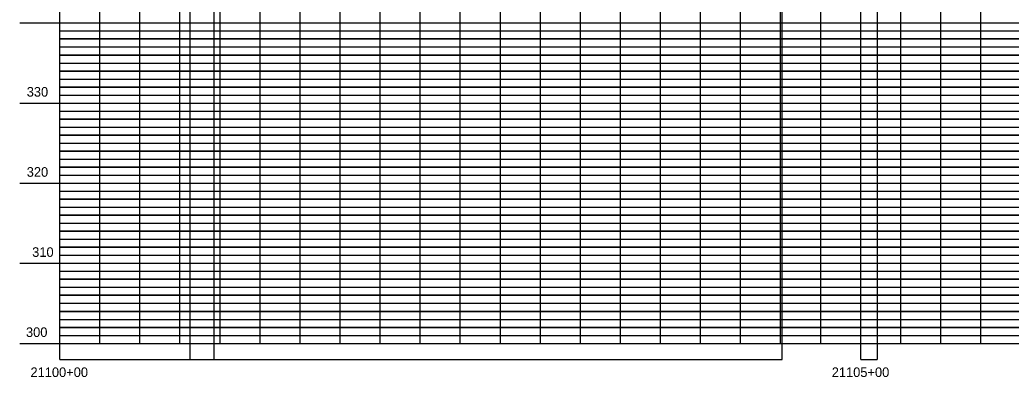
# Model space of a CAD drawing. Extents: x 1195880 to 1289360, y 2059330 to 2086925.
# Drawn here: x 1196981 to 1197600, y 2059330 to 2059553 of the extents above; entities that cross this region are included whole.
import ezdxf

# ---------------------------------------------------------------- set-up
doc = ezdxf.new("R2010")
doc.units = 0
for name, color, linetype in [('51', 7, 'Continuous'), ('Default', 7, 'Continuous'), ('Grid', 7, 'Continuous'), ('Grid Lables', 7, 'Continuous')]:
    doc.layers.add(name, color=color, linetype=linetype)

msp = doc.modelspace()

# ---------------------------------------------------------------- linework, layer by layer
at = {"layer": 'Default'}
for p, q in [((1197102.55, 2059676.6), (1197102.55, 2059340.74)), ((1197087.81, 2059340.74), (1197087.81, 2059676.01)), ((1197457.27, 2059340.74), (1197457.27, 2059664.54)), ((1197516.64, 2059662.37), (1197516.64, 2059340.74)), ((1197006.37, 2059340.74), (1197087.81, 2059340.74)), ((1197006.37, 2059340.74), (1197457.27, 2059340.74)), ((1197006.37, 2059340.74), (1197102.55, 2059340.74)), ((1197506.37, 2059340.74), (1197516.64, 2059340.74))]:
    msp.add_line(p, q, dxfattribs=at)
at = {"layer": 'Grid'}
for p, q in [((1197006.37, 2059350.74), (1197006.37, 2059950.74)), ((1197031.37, 2059350.74), (1197031.37, 2059950.74)), ((1197056.37, 2059350.74), (1197056.37, 2059950.74)), ((1197081.37, 2059350.74), (1197081.37, 2059950.74)), ((1197106.37, 2059350.74), (1197106.37, 2059950.74)), ((1197131.37, 2059350.74), (1197131.37, 2059950.74)), ((1197156.37, 2059350.74), (1197156.37, 2059950.74)), ((1197181.37, 2059350.74), (1197181.37, 2059950.74)), ((1197206.37, 2059350.74), (1197206.37, 2059950.74)), ((1197231.37, 2059350.74), (1197231.37, 2059950.74)), ((1197256.37, 2059350.74), (1197256.37, 2059950.74)), ((1197281.37, 2059350.74), (1197281.37, 2059950.74)), ((1197306.37, 2059350.74), (1197306.37, 2059950.74)), ((1197331.37, 2059350.74), (1197331.37, 2059950.74)), ((1197356.37, 2059350.74), (1197356.37, 2059950.74)), ((1197381.37, 2059350.74), (1197381.37, 2059950.74)), ((1197406.37, 2059350.74), (1197406.37, 2059950.74)), ((1197431.37, 2059350.74), (1197431.37, 2059950.74)), ((1197456.37, 2059350.74), (1197456.37, 2059950.74)), ((1197481.37, 2059350.74), (1197481.37, 2059950.74)), ((1197506.37, 2059350.74), (1197506.37, 2059950.74)), ((1197531.37, 2059350.74), (1197531.37, 2059950.74)), ((1197556.37, 2059350.74), (1197556.37, 2059950.74)), ((1197581.37, 2059350.74), (1197581.37, 2059950.74)), ((1196981.37, 2059550.74), (1197006.37, 2059550.74)), ((1197006.37, 2059550.74), (1198006.37, 2059550.74)), ((1197006.37, 2059545.74), (1197009.37, 2059545.74)), ((1197006.37, 2059545.74), (1198006.37, 2059545.74)), ((1197006.37, 2059540.74), (1197009.37, 2059540.74)), ((1197006.37, 2059540.74), (1198006.37, 2059540.74)), ((1198006.37, 2059540.74), (1197006.37, 2059540.74)), ((1197006.37, 2059535.74), (1197009.37, 2059535.74)), ((1197006.37, 2059535.74), (1198006.37, 2059535.74)), ((1197006.37, 2059530.74), (1197009.37, 2059530.74)), ((1197006.37, 2059530.74), (1198006.37, 2059530.74)), ((1198006.37, 2059530.74), (1197006.37, 2059530.74)), ((1197006.37, 2059525.74), (1197009.37, 2059525.74)), ((1197006.37, 2059525.74), (1198006.37, 2059525.74)), ((1197006.37, 2059520.74), (1197009.37, 2059520.74)), ((1197006.37, 2059520.74), (1198006.37, 2059520.74)), ((1198006.37, 2059520.74), (1197006.37, 2059520.74)), ((1197006.37, 2059515.74), (1197009.37, 2059515.74)), ((1197006.37, 2059515.74), (1198006.37, 2059515.74)), ((1197006.37, 2059510.74), (1197009.37, 2059510.74)), ((1197006.37, 2059510.74), (1198006.37, 2059510.74)), ((1198006.37, 2059510.74), (1197006.37, 2059510.74)), ((1197006.37, 2059505.74), (1197009.37, 2059505.74)), ((1197006.37, 2059505.74), (1198006.37, 2059505.74)), ((1196981.37, 2059500.74), (1197006.37, 2059500.74)), ((1197006.37, 2059500.74), (1198006.37, 2059500.74)), ((1197006.37, 2059495.74), (1197009.37, 2059495.74)), ((1197006.37, 2059495.74), (1198006.37, 2059495.74)), ((1197006.37, 2059490.74), (1197009.37, 2059490.74)), ((1197006.37, 2059490.74), (1198006.37, 2059490.74)), ((1198006.37, 2059490.74), (1197006.37, 2059490.74)), ((1197006.37, 2059485.74), (1197009.37, 2059485.74)), ((1197006.37, 2059485.74), (1198006.37, 2059485.74)), ((1197006.37, 2059480.74), (1197009.37, 2059480.74)), ((1197006.37, 2059480.74), (1198006.37, 2059480.74)), ((1198006.37, 2059480.74), (1197006.37, 2059480.74)), ((1197006.37, 2059475.74), (1197009.37, 2059475.74)), ((1197006.37, 2059475.74), (1198006.37, 2059475.74)), ((1197006.37, 2059470.74), (1197009.37, 2059470.74)), ((1197006.37, 2059470.74), (1198006.37, 2059470.74)), ((1198006.37, 2059470.74), (1197006.37, 2059470.74)), ((1197006.37, 2059465.74), (1197009.37, 2059465.74)), ((1197006.37, 2059465.74), (1198006.37, 2059465.74)), ((1197006.37, 2059460.74), (1197009.37, 2059460.74)), ((1197006.37, 2059460.74), (1198006.37, 2059460.74)), ((1198006.37, 2059460.74), (1197006.37, 2059460.74)), ((1197006.37, 2059455.74), (1197009.37, 2059455.74)), ((1197006.37, 2059455.74), (1198006.37, 2059455.74)), ((1196981.37, 2059450.74), (1197006.37, 2059450.74)), ((1197006.37, 2059450.74), (1198006.37, 2059450.74)), ((1197006.37, 2059445.74), (1197009.37, 2059445.74)), ((1197006.37, 2059445.74), (1198006.37, 2059445.74)), ((1197006.37, 2059440.74), (1197009.37, 2059440.74)), ((1197006.37, 2059440.74), (1198006.37, 2059440.74)), ((1198006.37, 2059440.74), (1197006.37, 2059440.74)), ((1197006.37, 2059435.74), (1197009.37, 2059435.74)), ((1197006.37, 2059435.74), (1198006.37, 2059435.74)), ((1197006.37, 2059430.74), (1197009.37, 2059430.74)), ((1197006.37, 2059430.74), (1198006.37, 2059430.74)), ((1198006.37, 2059430.74), (1197006.37, 2059430.74)), ((1197006.37, 2059425.74), (1197009.37, 2059425.74)), ((1197006.37, 2059425.74), (1198006.37, 2059425.74)), ((1197006.37, 2059420.74), (1197009.37, 2059420.74)), ((1197006.37, 2059420.74), (1198006.37, 2059420.74)), ((1198006.37, 2059420.74), (1197006.37, 2059420.74)), ((1197006.37, 2059415.74), (1197009.37, 2059415.74)), ((1197006.37, 2059415.74), (1198006.37, 2059415.74)), ((1197006.37, 2059410.74), (1197009.37, 2059410.74)), ((1197006.37, 2059410.74), (1198006.37, 2059410.74)), ((1198006.37, 2059410.74), (1197006.37, 2059410.74)), ((1197006.37, 2059405.74), (1197009.37, 2059405.74)), ((1197006.37, 2059405.74), (1198006.37, 2059405.74)), ((1196981.37, 2059400.74), (1197006.37, 2059400.74)), ((1197006.37, 2059400.74), (1198006.37, 2059400.74)), ((1197006.37, 2059395.74), (1197009.37, 2059395.74)), ((1197006.37, 2059395.74), (1198006.37, 2059395.74)), ((1197006.37, 2059390.74), (1197009.37, 2059390.74)), ((1197006.37, 2059390.74), (1198006.37, 2059390.74)), ((1198006.37, 2059390.74), (1197006.37, 2059390.74)), ((1197006.37, 2059385.74), (1197009.37, 2059385.74)), ((1197006.37, 2059385.74), (1198006.37, 2059385.74)), ((1197006.37, 2059380.74), (1197009.37, 2059380.74)), ((1197006.37, 2059380.74), (1198006.37, 2059380.74)), ((1198006.37, 2059380.74), (1197006.37, 2059380.74)), ((1197006.37, 2059375.74), (1197009.37, 2059375.74)), ((1197006.37, 2059375.74), (1198006.37, 2059375.74)), ((1197006.37, 2059370.74), (1197009.37, 2059370.74)), ((1197006.37, 2059370.74), (1198006.37, 2059370.74)), ((1198006.37, 2059370.74), (1197006.37, 2059370.74)), ((1197006.37, 2059365.74), (1197009.37, 2059365.74)), ((1197006.37, 2059365.74), (1198006.37, 2059365.74)), ((1197006.37, 2059360.74), (1197009.37, 2059360.74)), ((1197006.37, 2059360.74), (1198006.37, 2059360.74)), ((1198006.37, 2059360.74), (1197006.37, 2059360.74)), ((1197006.37, 2059355.74), (1197009.37, 2059355.74)), ((1197006.37, 2059355.74), (1198006.37, 2059355.74)), ((1196981.37, 2059350.74), (1197006.37, 2059350.74)), ((1197006.37, 2059350.74), (1198006.37, 2059350.74)), ((1197006.37, 2059340.74), (1197006.37, 2059350.74)), ((1197031.37, 2059350.74), (1197031.37, 2059353.74)), ((1197056.37, 2059350.74), (1197056.37, 2059353.74)), ((1197081.37, 2059350.74), (1197081.37, 2059353.74)), ((1197106.37, 2059350.74), (1197106.37, 2059353.74)), ((1197131.37, 2059350.74), (1197131.37, 2059353.74)), ((1197156.37, 2059350.74), (1197156.37, 2059353.74)), ((1197181.37, 2059350.74), (1197181.37, 2059353.74)), ((1197206.37, 2059350.74), (1197206.37, 2059353.74)), ((1197231.37, 2059350.74), (1197231.37, 2059353.74)), ((1197256.37, 2059350.74), (1197256.37, 2059353.74)), ((1197281.37, 2059350.74), (1197281.37, 2059353.74)), ((1197306.37, 2059350.74), (1197306.37, 2059353.74)), ((1197331.37, 2059350.74), (1197331.37, 2059353.74)), ((1197356.37, 2059350.74), (1197356.37, 2059353.74)), ((1197381.37, 2059350.74), (1197381.37, 2059353.74)), ((1197406.37, 2059350.74), (1197406.37, 2059353.74)), ((1197431.37, 2059350.74), (1197431.37, 2059353.74)), ((1197456.37, 2059350.74), (1197456.37, 2059353.74)), ((1197481.37, 2059350.74), (1197481.37, 2059353.74)), ((1197506.37, 2059340.74), (1197506.37, 2059350.74)), ((1197531.37, 2059350.74), (1197531.37, 2059353.74)), ((1197556.37, 2059350.74), (1197556.37, 2059353.74)), ((1197581.37, 2059350.74), (1197581.37, 2059353.74))]:
    msp.add_line(p, q, dxfattribs=at)

# ---------------------------------------------------------------- texts
at = {"layer": '51'}
msp.add_text('-', height=0.0001, dxfattribs=at).set_placement((1197006.37, 2059350.74))
at = {"layer": 'Grid Lables'}
for s, p in [('330', (1196985.68, 2059504.74)), ('320', (1196985.68, 2059454.74)), ('310', (1196989.08, 2059404.74)), ('300', (1196985.21, 2059354.74)), ('21100+00', (1196988.02, 2059329.74)), ('21105+00', (1197488.26, 2059329.74))]:
    msp.add_text(s, height=6, dxfattribs=at).set_placement(p)

doc.saveas('drawing.dxf')
